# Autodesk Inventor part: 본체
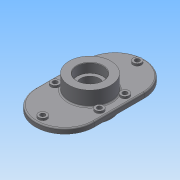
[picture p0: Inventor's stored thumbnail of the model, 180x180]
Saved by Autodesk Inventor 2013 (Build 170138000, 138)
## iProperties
Created: 2015-02
Part Number: 본체
Material: 일반
Document SubType Name: Modeling
Designer: ST4
Density: 1 g/cm^3
Author: ST4
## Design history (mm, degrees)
sketch "스케치1"
  geometry: L1 (70, 60)-(70, -60); L2 (-70, -60)-(-70, 60); A1 r 70 centre (0, 60) between (70, 60) and (-70, 60); A2 r 70 centre (0, -60) between (-70, -60) and (70, -60); 6 further points
  constraints: 5 point on circle, 4 end point, 3 vertical alignment, 2 centre point, 2 coincident, 2 horizontal alignment, 2 midpoint, 1 parallel
  dimensions: "d2" = 140 distance of L1.end L2.start; "d3" = 120 distance of L1.start L1.end; "d4" = 70 radius of A1; "d5" = 70 radius of A2
extrude "돌출1" new body sketch "스케치1" stored distance "d6" = 12; taper "d7" = 0 deg
sketch "스케치2"
  geometry: L1 (-70, 60)-(-70, -60) reference; L2 (70, -60)-(70, 60) reference; L3 (-53, 60)-(-53, -60); L4 (53, -60)-(53, 60); L5 (53, 37.5)-(53, -37.5); C1 r 10 at (0, 113); A1 r 70 centre (0, -60) between (-70, -60) and (70, -60) reference; A2 r 70 centre (0, 60) between (70, 60) and (-70, 60) reference; A3 r 53 centre (0, -60) between (-53, -60) and (53, -60); A4 r 53 centre (0, 60) between (53, 60) and (-53, 60); 3 further points
  constraints: 6 end point, 5 point on circle, 3 centre point, 1 coincident, 1 collinear, 1 horizontal alignment, 1 midpoint, 1 point on line, 1 vertical alignment, 3 other
  dimensions: "d8" = 17 distance between parallel lines of L2 L4; "d9" = 20 diameter of C1; "d21" = 75 distance of L5.end L5.start
extrude "돌출2" join sketch "스케치2" distance "d10" = 5; taper "d11" = 0 deg
hole "구멍1" diameter "d14" = 11; stored, may be unused: countersink angle "d18" = 90 deg, drill point angle "d20" = 118 deg; dims "d12" = 10, "d13" = 10, "d15" = 6, "d16" = 4, "d17" = 2, "d19" = 8
sketch "스케치3"
  geometry: L1 (70, -60)-(70, 60) reference; L2 (53, 30.49)-(53, -30.49); C1 r 10 at (53, 30.49); C2 r 10 at (53, -30.49); 2 further points
  constraints: 2 centre point, 2 coincident, 2 end point, 1 equal radius, 1 horizontal alignment, 1 midpoint, 1 parallel
  dimensions: "d22" = 60.97954 distance of L2.end L2.start; "d23" = 53 horizontal distance of point (0, 0) L2.end; "d24" = 20 diameter of C1
extrude "돌출3" join sketch "스케치3" distance "d25" = 5; taper "d26" = 0 deg
hole "구멍2" diameter "d29" = 11; stored, may be unused: countersink angle "d33" = 90 deg, drill point angle "d35" = 118 deg; dims "d27" = 10, "d28" = 10, "d30" = 6, "d31" = 4, "d32" = 2, "d34" = 8
hole "구멍3" diameter "d38" = 11; stored, may be unused: countersink angle "d42" = 90 deg, drill point angle "d44" = 118 deg; dims "d36" = 10, "d37" = 10, "d39" = 6, "d40" = 4, "d41" = 2, "d43" = 8
sketch "스케치4"
  geometry: C1 r 50 at (0, 0); 1 further point
  constraints: 1 centre point, 1 coincident
  dimensions: "d45" = 100 diameter of C1
extrude "돌출4" join sketch "스케치4" distance "d47" = 35; taper "d48" = 0 deg
sketch "스케치5"
  geometry: C1 r 50 at (0, 0); 1 further point
  constraints: 1 centre point, 1 coincident
  dimensions: "d49" = 100 diameter of C1
extrude "돌출5" join sketch "스케치5" distance "d51" = 23; taper "d52" = 0 deg
hole "구멍4" diameter "d55" = 45; stored, may be unused: countersink angle "d59" = 90 deg, drill point angle "d61" = 0 deg; dims "d53" = 10, "d54" = 10, "d56" = 6, "d57" = 62, "d58" = 22, "d60" = 8
hole "구멍5" diameter "d64" = 62; stored, may be unused: countersink angle "d68" = 90 deg, drill point angle "d70" = 0 deg; dims "d62" = 10, "d63" = 10, "d65" = 6, "d66" = 62, "d67" = 22, "d69" = 22
sketch "스케치6"
  geometry: L1 (0, 0)-(-13.231, 0); C1 r 31 at (0, 0) reference; C2 r 50 at (0, 0) reference; 1 further point
  constraints: 2 end point, 1 horizontal
  dimensions: "d71" = 41 distance of point (-28.991, 28.991) C1.centre; "d72" = 45 deg dimension on C1.centre point (-28.991, 28.991) L1.end; "d73" = 13.23083 distance of L1.start L1.end
hole "구멍6" sketch "스케치6" at (-28.991, 28.991) diameter "d74" = 4.917; stored, may be unused: countersink angle "d78" = 90 deg, drill point angle "d80" = 118 deg; dims "d75" = 10, "d76" = 62, "d77" = 22, "d79" = 13
fillet "모깎기1" dims "d84" = 3
fillet "모깎기2" dims "d85" = 3
chamfer "모따기1" distance "d86" = 1; stored, may be unused: second distance "d87" = 2, angle "d88" = 45 deg
chamfer "모따기2" distance "d89" = 1; stored, may be unused: second distance "d90" = 2, angle "d91" = 45 deg
fillet "모깎기3" dims "d92" = 0.3
node "솔리드1"
mirror "대칭1"
mirror "대칭2"
pattern_circular "원형 패턴1" dims angle "d82" = 360 deg
